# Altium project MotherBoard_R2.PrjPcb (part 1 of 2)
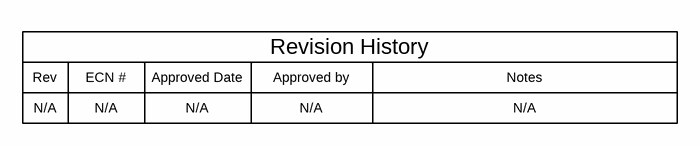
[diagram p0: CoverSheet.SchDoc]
CopyrightYear: 2020; PCB_Layout: Ramesh Ramamoorthy; PCB_Rev: E2; PRJ_Customer: EV Traction; PRJ_Engineer: Ramesh Ramamoorthy; PRJ_Number: EVT_001; PRJ_Title: EV Traction Control Mother Board; SCH_Rev: E2; TechSupport: http://www.ti.com/support; TID: TIDM-02009
7 sheets, 208 parts. Net scope: global (net labels, ports and power ports of the same name join across sheets).
Board file: MotherBoard_R2.PcbDoc
Sheets:
  CoverSheet.SchDoc
  Hardware.SchDoc
  ChildBoardMotor_r2.SchDoc
  MotherBoard_r2.SchDoc
  ChildBoardDC-DC_r2.SchDoc
  powerSupplyAndMontior_r1.SchDoc
  ChildBoardComms_r3.SchDoc

## Sheet CoverSheet.SchDoc
size 431 x 279 mm; Date: Not shown in title block; ApprovedBy: Not shown in title block; CheckedBy: Not shown in title block; Author: Not shown in title block; CompanyName: Not shown in title block; Engineer: Not shown in title block; Organization: Not shown in title block; Address1: Not shown in title block; Address2: Not shown in title block; Address3: Not shown in title block; Address4: Not shown in title block; DocumentNumber: 1; Revision: Use project parameter SCH_Rev; SheetNumber: 1; SheetTotal: 3; PageSetup: Record=PageOptions¦CenterHorizontal=True¦CenterVertical=True¦PrintScale=1.00¦XCorrection=1.00¦YCorrection=1.00¦PrintKind=0¦BorderSize=5000000¦LeftOffset=0¦BottomOffset=0¦Orientation=2¦PaperLength=1000¦PaperWidth=1000¦Scale=100¦PaperSource=15¦PrintQuality=600¦MediaType=1¦DitherType=10¦PaperKind=Letter¦PrintScaleMode=1

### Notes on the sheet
- Rev
- N/A
- ECN #
- Approved Date
- Approved by
- Revision History
- Notes

## Sheet Hardware.SchDoc
size 431 x 279 mm; Date: Not shown in title block; ApprovedBy: Not shown in title block; CheckedBy: Not shown in title block; Author: Not shown in title block; CompanyName: Not shown in title block; Engineer: Not shown in title block; Organization: Not shown in title block; Address1: Not shown in title block; Address2: Not shown in title block; Address3: Not shown in title block; Address4: Not shown in title block; DocumentNumber: 3; Revision: Use project parameter SCH_Rev; SheetNumber: 3; SheetTotal: 3; PageSetup: Record=PageOptions¦CenterHorizontal=True¦CenterVertical=True¦PrintScale=1.00¦XCorrection=1.00¦YCorrection=1.00¦PrintKind=0¦BorderSize=5000000¦LeftOffset=0¦BottomOffset=0¦Orientation=2¦PaperLength=1000¦PaperWidth=1000¦Scale=100¦PaperSource=15¦PrintQuality=600¦MediaType=1¦DitherType=10¦PaperKind=Letter¦PrintScaleMode=1
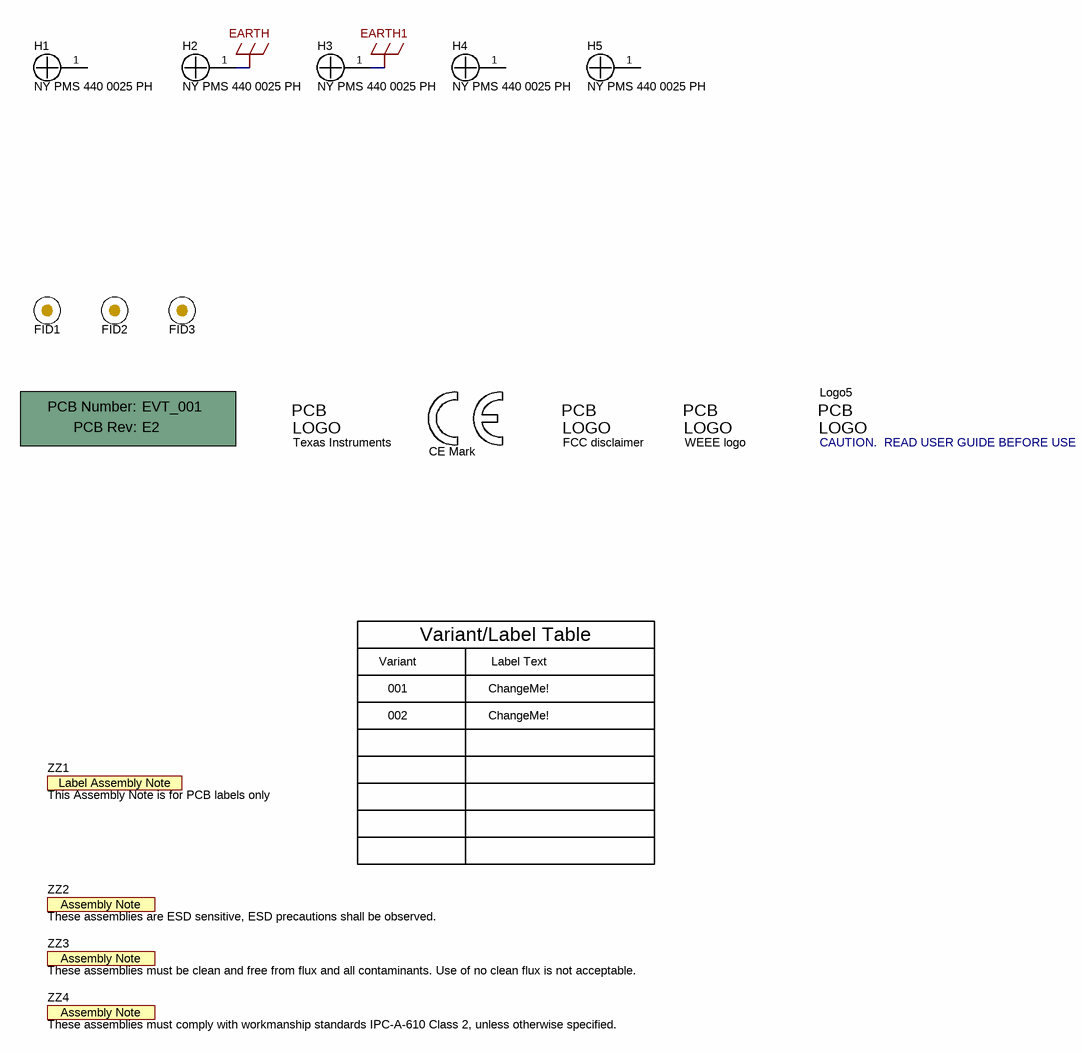
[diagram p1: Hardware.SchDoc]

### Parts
!PCB  Printed Circuit Board  (value not drawn)  (mechanical)
FID1  Fiducial  [Fiducial10-20]  (value not drawn)
FID2  Fiducial  [Fiducial10-20]  (value not drawn)
FID3  Fiducial  [Fiducial10-20]  (value not drawn)
H1  NY PMS 440 0025 PH  [NY PMS 440 0025 PH]
H2  NY PMS 440 0025 PH  [NY PMS 440 0025 PH]
H3  NY PMS 440 0025 PH  [NY PMS 440 0025 PH]
H4  NY PMS 440 0025 PH  [NY PMS 440 0025 PH]
H5  NY PMS 440 0025 PH  [NY PMS 440 0025 PH]
Logo1  Texas Instruments  [TI_Stacked_Overlay_Medium]  (no BOM)
Logo2  CE Mark  [CE_Mark_5mm]  (no BOM)
Logo3  FCC disclaimer  [FCC_disclaimer]  (no BOM)
Logo4  WEEE logo  [WEEE_Minimum]  (no BOM)
Logo5  CAUTION.  READ USER GUIDE BEFORE USE  [IEC_Caution_Small]  (no BOM)
ZZ1  This Assembly Note is for PCB labels only  [AssemblyNoteLabel]  (no BOM)
ZZ2  These assemblies are ESD sensitive, ESD precautions shall be observed.  [AssemblyNote]  (no BOM)
ZZ3  These assemblies must be clean and free from flux and all contaminants. Use of no clean flux is not acceptable.  [AssemblyNote]  (no BOM)
ZZ4  These assemblies must comply with workmanship standards IPC-A-610 Class 2, unless otherwise specified.  [AssemblyNote]  (no BOM)

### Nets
EARTH: H2.1
EARTH1: H3.1

Not connected (* = marked no-connect by the designer): H1 1; H4 1; H5 1

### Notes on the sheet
- Variant
- Variant/Label Table
- Label Text
- 001
- 002
- ChangeMe!

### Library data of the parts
!PCB = CMP-0003618-2: Manufacturer: Any; PartNumber: EVT_001
FID1-FID3 = CMP-0077181-1: Fiducial mark.  There is nothing to buy or mount.
H1-H5 = CMP-0003617-1: Machine Screw, Round, #4-40 x 1/4, Nylon, Philips panhead; Manufacturer: B&F Fastener Supply; CompType: Hardware
Logo1 = CMP-0074838-1: Texas Instrument Corporate Signature; SymbolCreator: a0412235; Lib Reference: TI_Logo; Library Reference: Logo
Logo2 = CMP-0074844-1: SymbolCreator: a0412235
Logo3 = CMP-0074847-1: FCC_disclaimer; Library Reference: Logo
Logo4 = CMP-0074769-1
Logo5 = CMP-0074836-1: IEC 61010-1 Caution Warning; SymbolCreator: a0412235; Lib Reference: IEC_Caution
ZZ1 = CMP-0003616-3
ZZ2 = CMP-0077236-1
ZZ3 = CMP-0077237-1
ZZ4 = CMP-0077238-1

## Sheet ChildBoardMotor_r2.SchDoc
size 431 x 279 mm; Date: Not shown in title block; ApprovedBy: Not shown in title block; CheckedBy: Not shown in title block; Author: Not shown in title block; CompanyName: Not shown in title block; Engineer: Not shown in title block; Organization: Not shown in title block; Address1: Not shown in title block; Address2: Not shown in title block; Address3: Not shown in title block; Address4: Not shown in title block; DocumentNumber: 2; Revision: Use project parameter SCH_Rev; SheetNumber: 2; SheetTotal: 3; PageSetup: Record=PageOptions¦CenterHorizontal=True¦CenterVertical=True¦PrintScale=1.00¦XCorrection=1.00¦YCorrection=1.00¦PrintKind=0¦BorderSize=5000000¦LeftOffset=0¦BottomOffset=0¦Orientation=2¦PaperLength=1000¦PaperWidth=1000¦Scale=100¦PaperSource=15¦PrintQuality=600¦MediaType=1¦DitherType=10¦PaperKind=Letter¦PrintScaleMode=1
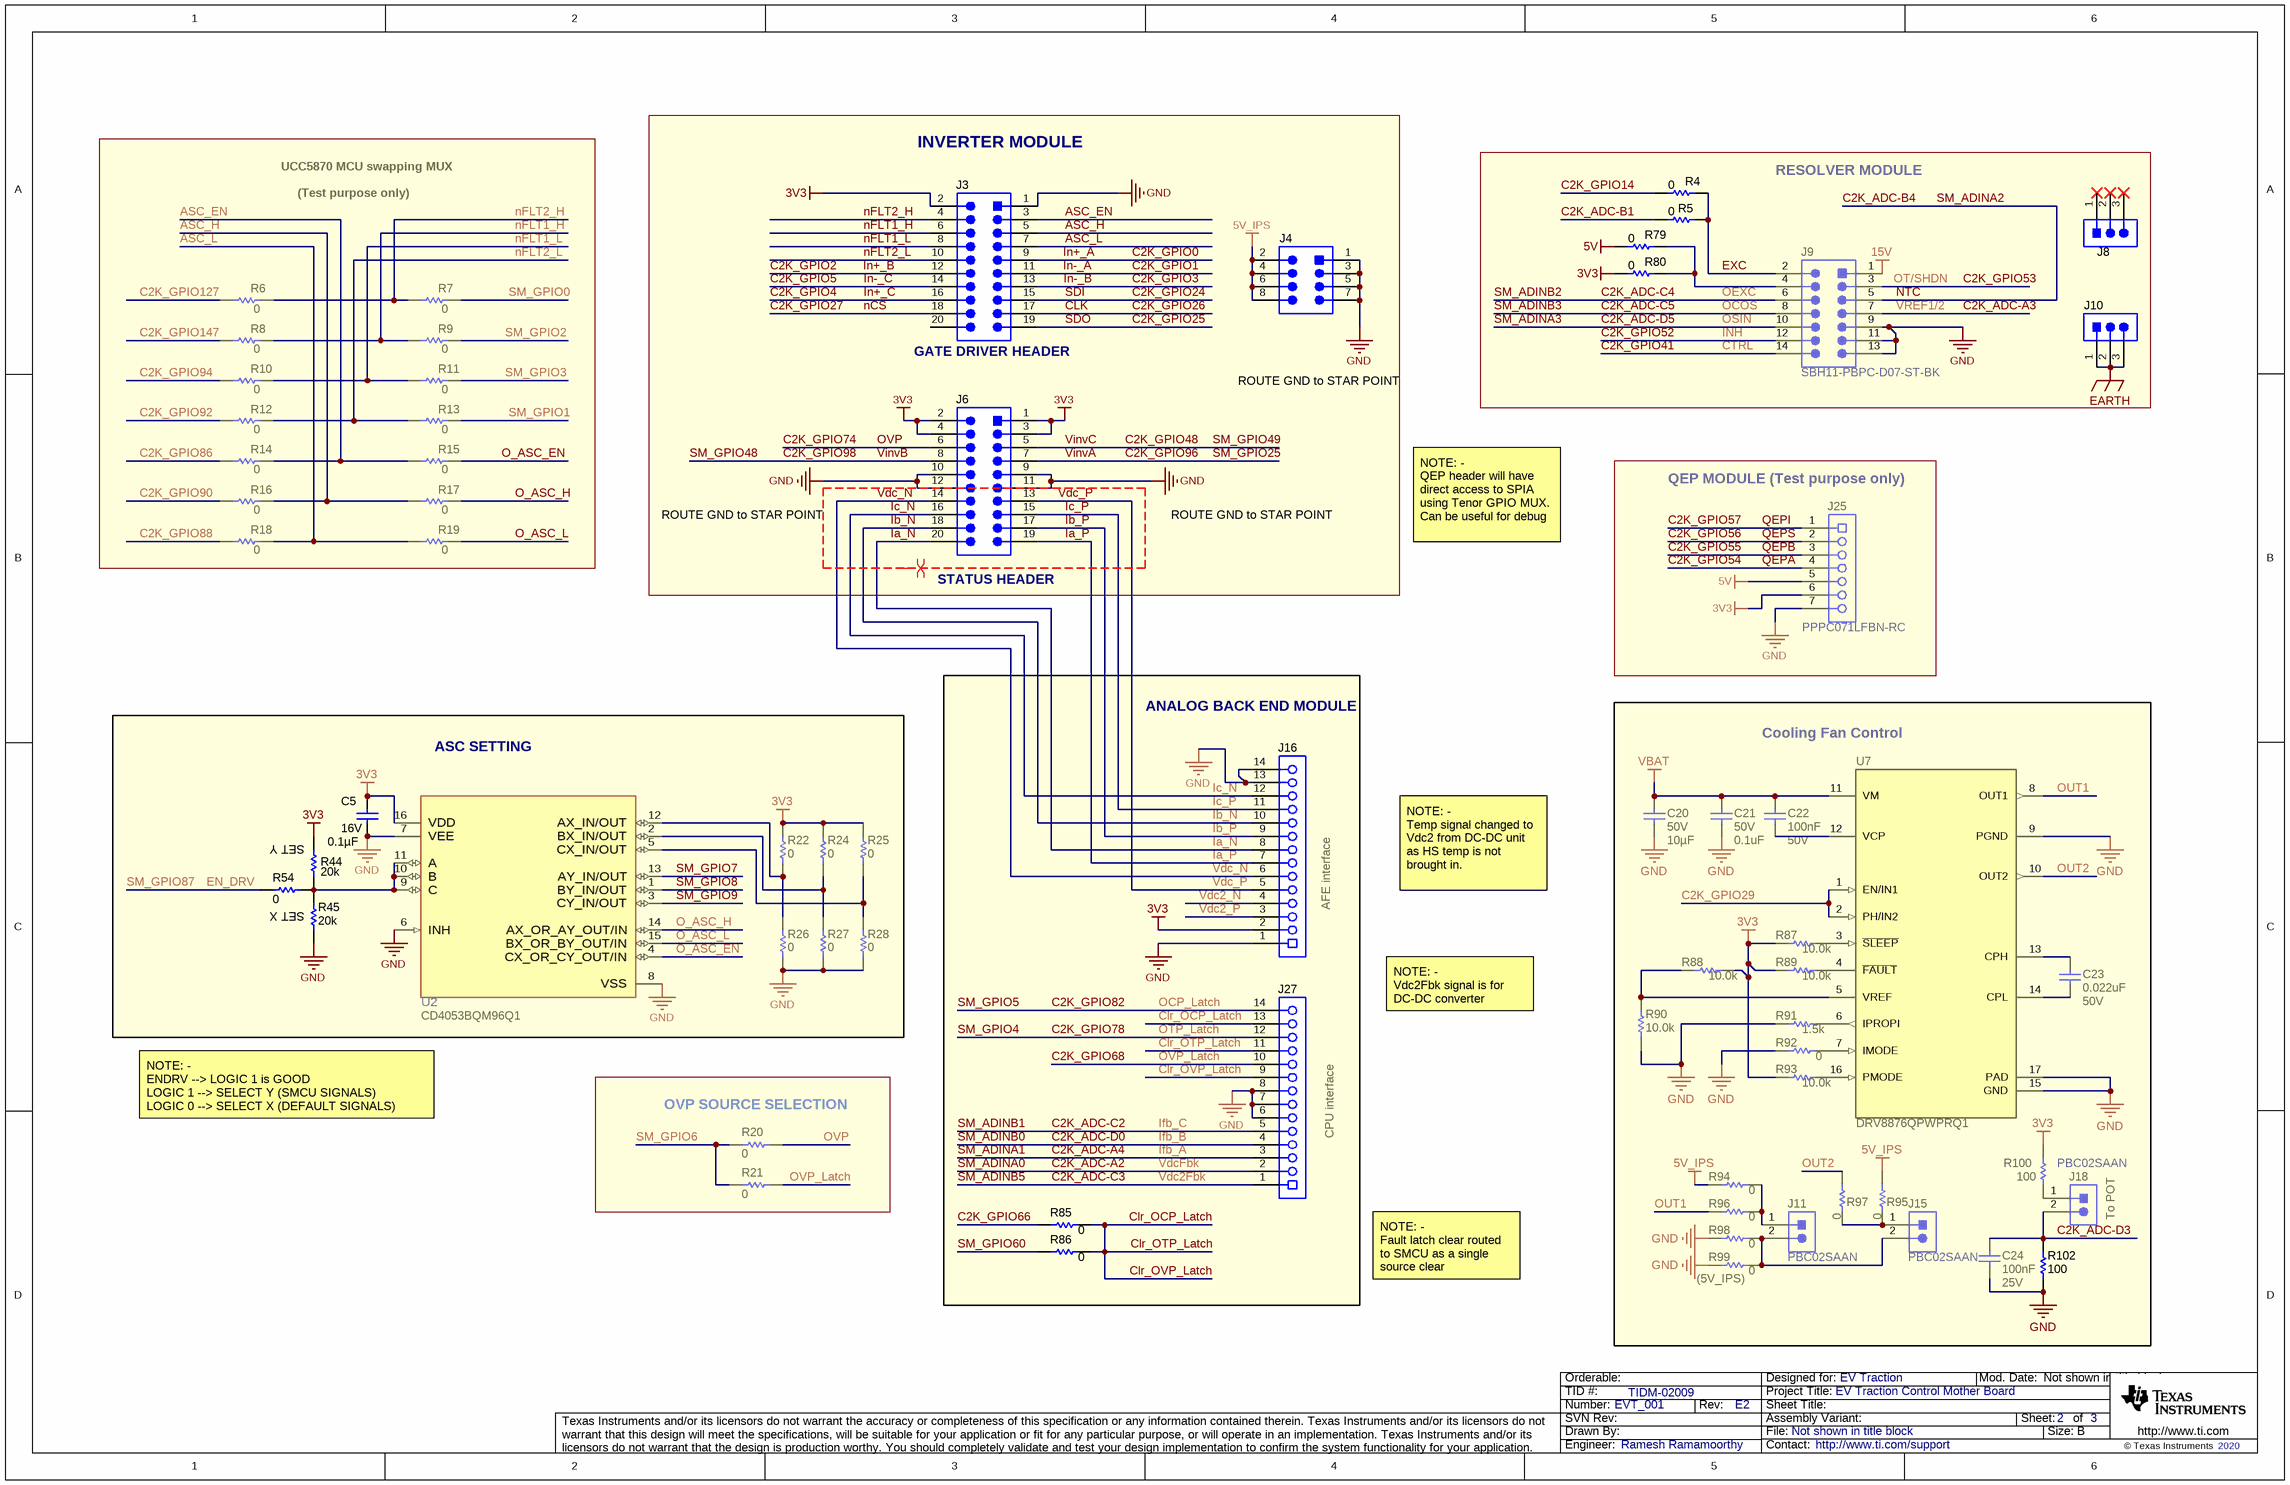
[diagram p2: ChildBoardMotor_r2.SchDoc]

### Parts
C5  VDC_V: 16V  ValueDisplayed: 0.1µF  [1206]  (hidden comment: 1206YC104KAT2A)
C20  VDC_V: 50V  ValueDisplayed: 10µF  [1210_280]  (hidden comment: UMJ325KB7106MMHP)
C21  VDC_V: 50V  ValueDisplayed: 0.1uF  [1206]  (hidden comment: GRM319R71H104KA01D)
C22  Cap_F: 100nF  VDC_V: 50V  [0603L]  (hidden comment: 885012206095)
C23  ValueDisplayed: 0.022uF  VDC_V: 50V  [0603L]  (hidden comment: 885012206091)
C24  Cap_F: 100nF  VDC_V: 25V  [0805_HV]  (hidden comment: SR0805X7R104K1NT95(F)#M123A)
J3  SBH11-PBPC-D10-RA-BK  [Sullins_SBH11-xxxC-D10-RA]  (value not drawn)
J4  61300821021  [Wurth_61300821021]  (value not drawn)
J6  SBH11-PBPC-D10-RA-BK  [Sullins_SBH11-xxxC-D10-RA]  (value not drawn)
J8  61300311121  [WURTH_61300311121]  (value not drawn)
J9  SBH11-PBPC-D07-ST-BK  [CONN_SBH11-PBPC-D07-ST-BK]
J10  61300311121  [WURTH_61300311121]  (value not drawn)
J11  PBC02SAAN  [Sullins_PBC02SAAN]
J15  PBC02SAAN  [Sullins_PBC02SAAN]
J16  SSW-114-01-G-S  [Samtec_SSW-114-01-x-S]  (value not drawn)
J18  PBC02SAAN  [Sullins_PBC02SAAN]
J25  PPPC071LFBN-RC  [Sullins_xPxC071LFBN]
J27  SSW-114-01-G-S  [Samtec_SSW-114-01-x-S]  (value not drawn)
R4  ValueDisplayed: 0  [0805_HV]  (hidden comment: ERJ-6GEY0R00V)
R5  ValueDisplayed: 0  [0805_HV]  (hidden comment: ERJ-6GEY0R00V)
R6  ValueDisplayed: 0  [0805_HV]  (hidden comment: ERJ-6GEY0R00V)
R7  ValueDisplayed: 0  [0805_HV]  (hidden comment: ERJ-6GEY0R00V)
R8  ValueDisplayed: 0  [0805_HV]  (hidden comment: ERJ-6GEY0R00V)
R9  ValueDisplayed: 0  [0805_HV]  (hidden comment: ERJ-6GEY0R00V)
R10  ValueDisplayed: 0  [0805_HV]  (hidden comment: ERJ-6GEY0R00V)
R11  ValueDisplayed: 0  [0805_HV]  (hidden comment: ERJ-6GEY0R00V)
R12  ValueDisplayed: 0  [0805_HV]  (hidden comment: ERJ-6GEY0R00V)
R13  ValueDisplayed: 0  [0805_HV]  (hidden comment: ERJ-6GEY0R00V)
R14  ValueDisplayed: 0  [0805_HV]  (hidden comment: ERJ-6GEY0R00V)
R15  ValueDisplayed: 0  [0805_HV]  (hidden comment: ERJ-6GEY0R00V)
R16  ValueDisplayed: 0  [0805_HV]  (hidden comment: ERJ-6GEY0R00V)
R17  ValueDisplayed: 0  [0805_HV]  (hidden comment: ERJ-6GEY0R00V)
R18  ValueDisplayed: 0  [0805_HV]  (hidden comment: ERJ-6GEY0R00V)
R19  ValueDisplayed: 0  [0805_HV]  (hidden comment: ERJ-6GEY0R00V)
R20  ValueDisplayed: 0  [1206]  (hidden comment: RCA12060000ZSEA)
R21  ValueDisplayed: 0  [1206]  (hidden comment: RCA12060000ZSEA)
R22  ValueDisplayed: 0  [0805_HV]  (hidden comment: ERJ-6GEY0R00V)
R24  ValueDisplayed: 0  [0805_HV]  (hidden comment: ERJ-6GEY0R00V)
R25  ValueDisplayed: 0  [0805_HV]  (hidden comment: ERJ-6GEY0R00V)
R26  ValueDisplayed: 0  [0805_HV]  (hidden comment: ERJ-6GEY0R00V)
R27  ValueDisplayed: 0  [0805_HV]  (hidden comment: ERJ-6GEY0R00V)
R28  ValueDisplayed: 0  [0805_HV]  (hidden comment: ERJ-6GEY0R00V)
R44  ValueDisplayed: 20k  [0805_HV]  (hidden comment: ERJ-6GEYJ203V)
R45  ValueDisplayed: 20k  [0805_HV]  (hidden comment: ERJ-6GEYJ203V)
R54  ValueDisplayed: 0  [0805_HV]  (hidden comment: ERJ-6GEY0R00V)
R79  ValueDisplayed: 0  [0805_HV]  (hidden comment: ERJ-6GEY0R00V)
R80  ValueDisplayed: 0  [0805_HV]  (hidden comment: ERJ-6GEY0R00V)
R85  ValueDisplayed: 0  [1206]  (hidden comment: RCA12060000ZSEA)
R86  ValueDisplayed: 0  [1206]  (hidden comment: RCA12060000ZSEA)
R87  ValueDisplayed: 10.0k  [0603L]  (hidden comment: ERA-3ARW103V)
R88  ValueDisplayed: 10.0k  [0603L]  (hidden comment: ERA-3ARW103V)
R89  ValueDisplayed: 10.0k  [0603L]  (hidden comment: ERA-3ARW103V)
R90  ValueDisplayed: 10.0k  [0603L]  (hidden comment: ERA-3ARW103V)
R91  ValueDisplayed: 1.5k  [0603L]  (hidden comment: CRCW06031K50JNEA)
R92  ValueDisplayed: 0  [0603L]  (hidden comment: ERJ-3GEY0R00V)
R93  ValueDisplayed: 10.0k  [0603L]  (hidden comment: ERA-3ARW103V)
R94  ValueDisplayed: 0  [0603L]  (hidden comment: ERJ-3GEY0R00V)
R95  ValueDisplayed: 0  [0603L]  (hidden comment: ERJ-3GEY0R00V)
R96  ValueDisplayed: 0  [0603L]  (hidden comment: ERJ-3GEY0R00V)
R97  ValueDisplayed: 0  [0603L]  (hidden comment: ERJ-3GEY0R00V)
R98  ValueDisplayed: 0  [0603L]  (hidden comment: ERJ-3GEY0R00V)
R99  ValueDisplayed: 0  [0603L]  (hidden comment: ERJ-3GEY0R00V)
R100  ValueDisplayed: 100  [0805_HV]  (hidden comment: CRCW0805100RFKEA)
R102  ValueDisplayed: 100  [0805_HV]  (hidden comment: CRCW0805100RFKEA)
U2  CD4053BQM96Q1  [D0016A-MFG]
U7  DRV8876QPWPRQ1  [PWP0016J_N]

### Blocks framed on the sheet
INVERTER MODULE: J3 J4 J6
RESOLVER MODULE: J8-J10 R4 R5 R79 R80
QEP MODULE (Test purpose only): J25
ANALOG BACK END MODULE: J16 J27 R85 R86
ASC SETTING: C5 R22 R24-R28 R44 R45 R54 U2
Cooling Fan Control: C20-C24 J11 J15 J18 R87-R100 R102 U7
OVP SOURCE SELECTION: R20 R21

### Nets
3V3: C5.1 J3.2 J6.1 J6.2 J6.3 J6.4 J16.2 J25.6 R22.2 R24.2 R25.2 R44.2 R80.1 R87.1 R88.2 R89.1 R93.1 R100.2 U2.16(VDD)
5V: J25.5 R79.1
5V_IPS: J4.2 J4.4 J4.6 J4.8 R94.1 R95.1
15V: J9.1
EARTH: J10.1 J10.2 J10.3
GND: C5.2 C20.2 C21.2 C24.1 J3.1 J4.1 J4.3 J4.5 J4.7 J6.9 J6.10 J6.11 J6.12 J9.9 J9.11 J9.13 J16.1 J16.13 J16.14 J25.7 J27.6 J27.7 J27.8 R26.1 R27.1 R28.1 R45.1 R90.1 R91.1 R92.1 R98.1 R99.1 R102.1 U2.6(INH) U2.7(VEE) U2.8(VSS) U7.9(PGND) U7.15(GND) U7.17(PAD)
VBAT: C20.1 C21.1 C22.1 U7.11(VM)
ASC_EN: J3.3 R14.2 R15.1
ASC_H: J3.5 R16.2 R17.1
ASC_L: J3.7 R18.2 R19.1
C2K_ADC-A2: J27.2  [also labelled SM_ADINA0, VdcFbk]
C2K_ADC-A3: J9.7  [also labelled VREF1/2]
C2K_ADC-A4: J27.3  [also labelled Ifb_A, SM_ADINA1]
C2K_ADC-B1: R5.1
C2K_ADC-B4: J9.5  [also labelled NTC, SM_ADINA2]
C2K_ADC-C2: J27.5  [also labelled Ifb_C, SM_ADINB1]
C2K_ADC-C3: J27.1  [also labelled SM_ADINB5, Vdc2Fbk]
C2K_ADC-C4: J9.6  [also labelled OEXC, SM_ADINB2]
C2K_ADC-C5: J9.8  [also labelled OCOS, SM_ADINB3]
C2K_ADC-D0: J27.4  [also labelled Ifb_B, SM_ADINB0]
C2K_ADC-D3: C24.2 J18.2 R102.2
C2K_ADC-D5: J9.10  [also labelled OSIN, SM_ADINA3]
C2K_GPIO0: J3.9  [also labelled In+_A]
C2K_GPIO1: J3.11  [also labelled In-_A]
C2K_GPIO2: J3.12  [also labelled In+_B]
C2K_GPIO3: J3.13  [also labelled In-_B]
C2K_GPIO4: J3.16  [also labelled In+_C]
C2K_GPIO5: J3.14  [also labelled In-_C]
C2K_GPIO14: R4.1
C2K_GPIO24: J3.15  [also labelled SDI]
C2K_GPIO25: J3.19  [also labelled SDO]
C2K_GPIO26: J3.17  [also labelled CLK]
C2K_GPIO27: J3.18  [also labelled nCS]
C2K_GPIO29: U7.1(EN/IN1) U7.2(PH/IN2)
C2K_GPIO41: J9.14  [also labelled CTRL]
C2K_GPIO48: J6.5  [also labelled SM_GPIO49, VinvC]
C2K_GPIO52: J9.12  [also labelled INH]
C2K_GPIO53: J9.3  [also labelled OT/SHDN]
C2K_GPIO54: J25.4  [also labelled QEPA]
C2K_GPIO55: J25.3  [also labelled QEPB]
C2K_GPIO56: J25.2  [also labelled QEPS]
C2K_GPIO57: J25.1  [also labelled QEPI]
C2K_GPIO66: R85.1
C2K_GPIO68: J27.10 R21.2  [also labelled OVP_Latch]
C2K_GPIO74: J6.6 R20.2  [also labelled OVP]
C2K_GPIO78: J27.12  [also labelled OTP_Latch, SM_GPIO4]
C2K_GPIO82: J27.14  [also labelled OCP_Latch, SM_GPIO5]
C2K_GPIO86: R14.1
C2K_GPIO88: R18.1
C2K_GPIO90: R16.1
C2K_GPIO92: R12.1
C2K_GPIO94: R10.1
C2K_GPIO96: J6.7  [also labelled SM_GPIO25, VinvA]
C2K_GPIO98: J6.8  [also labelled SM_GPIO48, VinvB]
C2K_GPIO127: R6.1
C2K_GPIO147: R8.1
Clr_OCP_Latch: J27.9 J27.11 J27.13 R85.2 R86.2  [also labelled Clr_OTP_Latch, Clr_OVP_Latch]
EN_DRV: R54.2  [also labelled SM_GPIO87]
EXC: J9.2 R4.2 R5.2
Ia_N: J6.20 J16.8
Ia_P: J6.19 J16.7
Ib_N: J6.18 J16.10
Ib_P: J6.17 J16.9
Ic_N: J6.16 J16.12
Ic_P: J6.15 J16.11
nFLT1_H: J3.6 R8.2 R9.1
nFLT1_L: J3.8 R10.2 R11.1
nFLT2_H: J3.4 R6.2 R7.1
nFLT2_L: J3.10 R12.2 R13.1
O_ASC_EN: R15.2 U2.4(CX_OR_CY_OUT/IN)
O_ASC_H: R17.2 U2.14(AX_OR_AY_OUT/IN)
O_ASC_L: R19.2 U2.15(BX_OR_BY_OUT/IN)
OUT1: R96.1 U7.8(OUT1)
OUT2: R97.1 U7.10(OUT2)
SM_GPIO0: R7.2
SM_GPIO1: R13.2
SM_GPIO2: R9.2
SM_GPIO3: R11.2
SM_GPIO6: R20.1 R21.1
SM_GPIO7: U2.13(AY_IN/OUT)
SM_GPIO8: U2.1(BY_IN/OUT)
SM_GPIO9: U2.3(CY_IN/OUT)
SM_GPIO60: R86.1
Vdc2_N: J16.4
Vdc2_P: J16.3
Vdc_N: J6.14 J16.6
Vdc_P: J6.13 J16.5
NetC22_2: C22.2 U7.12(VCP)
NetC23_1: C23.1 U7.13(CPH)
NetC23_2: C23.2 U7.14(CPL)
NetJ9_4: J9.4 R79.2 R80.2
NetJ11_1: J11.1 R94.2 R96.2
NetJ11_2: J11.2 J15.2 R98.2 R99.2
NetJ15_1: J15.1 R95.2 R97.2
NetJ18_1: J18.1 R100.1
NetR22_1: R22.1 R26.2 U2.12(AX_IN/OUT)
NetR24_1: R24.1 R27.2 U2.2(BX_IN/OUT)
NetR25_1: R25.1 R28.2 U2.5(CX_IN/OUT)
NetR44_1: R44.1 R45.2 R54.1 U2.9(C) U2.10(B) U2.11(A)
NetR87_2: R87.2 U7.3(~{SLEEP})
NetR88_1: R88.1 R90.2 U7.5(VREF)
NetR89_2: R89.2 U7.4(~{FAULT})
NetR91_2: R91.2 U7.6(IPROPI)
NetR92_2: R92.2 U7.7(IMODE)
NetR93_2: R93.2 U7.16(PMODE)

Not connected (* = marked no-connect by the designer): J3 20; J8 1* 2* 3*

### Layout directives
differential pair: Ia_N, Ia_P, Ib_N, Ib_P, Ic_N, Ic_P, Vdc_N, Vdc_P

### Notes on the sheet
- UCC5870 MCU swapping MUX
- (Test purpose only)
- (near J3) GATE DRIVER HEADER
- ROUTE GND to STAR POINT
- NOTE: -
  QEP header will have direct access to SPIA using Tenor GPIO MUX. Can be useful for debug
- (near J6) STATUS HEADER
- (near R44) SET Y
- (near J16) AFE interface
- NOTE: -
  Temp signal changed to Vdc2 from DC-DC unit as HS temp is not brought in.
- SET X
- NOTE: -
  Vdc2Fbk signal is for DC-DC converter
- (near J27) CPU interface
- NOTE: -
  ENDRV --> LOGIC 1 is GOOD
  LOGIC 1 --> SELECT Y (SMCU SIGNALS)
  LOGIC 0 --> SELECT X (DEFAULT SIGNALS)
- (near J18) To POT
- NOTE: -
  Fault latch clear routed to SMCU as a single source clear
- (near R99) (5V_IPS)

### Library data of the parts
C5 = CMP-0860522-1: CAP, CERM, 0.1 µF, 16 V,+/- 10%, X7R, 1206; Manufacturer: AVX; SizeArea_mm2: 5.12; SizeX_mm: 3.2; Value: 0.1uF; SizeAreaWB_mm2: 10.92; Cap_F: 100nF; SizeZ_mm: 1.35; AEC Category: Q200; Polarized: N; U/M: EA; SizeY_mm: 1.6; TaMin_C: -55°C; TaMax_C: 125°C
C20 = CMP-0082302-1: CAP, CERM, 10 µF, 50 V,+/- 20%, X7R, AEC-Q200 Grade 1, 1210; Manufacturer: Taiyo Yuden; SizeAreaWB_mm2: 14.7; SizeArea_mm2: 8; AEC Qualified: Y; AEC Category: Q200; Value: 10uF; TaMax_C: 125°C; SizeZ_mm: 2.8; AEC Grade: 1; Polarized: N; TaMin_C: -55°C; SizeY_mm: 2.5; U/M: EA; SizeX_mm: 3.2; Cap_Case: 1210
C21 = CMP-0008876-1: CAP, CERM, 0.1 uF, 50 V, +/- 10%, X7R, 1206; Manufacturer: MuRata; TaMin_C: -55°C; ESR_ohm: 0.01; Polarized: N; SizeAreaWB_mm2: 10.92; Value1: 0.01 ohm; U/M: EA; Value: 0.1uF; TaMax_C: 125°C; SizeZ_mm: 1.35; SizeX_mm: 3.2; SizeY_mm: 1.6; SizeArea_mm2: 5.12; Cap_F: 100nF; IRMS_A: 900mA; AEC Category: Q200
C22 = CMP-0006837-4: CAP, CERM, 0.1 uF, 50 V, +/- 10%, X7R, 0603; Manufacturer: Wurth Elektronik; Polarized: N; Value: 0.1uF; U/M: EA; Value1: Unknown; TaMin_C: -55°C; TaMax_C: 125°C; Cap_Case: 0603; SizeArea_mm2: 1.28; SizeAreaWB_mm2: 4.68; SizeX_mm: 1.6; SizeY_mm: 0.8; SizeZ_mm: 1; AEC Category: Q200
C23 = CMP-0006836-4: CAP, CERM, 0.022 uF, 50 V, +/- 10%, X7R, 0603; Manufacturer: Wurth Elektronik; Polarized: N; U/M: EA; Cap_F: 22nF; Value1: Unknown; TaMin_C: -55°C; TaMax_C: 125°C; Cap_Case: 0603; SizeArea_mm2: 1.28; SizeAreaWB_mm2: 4.68; SizeX_mm: 1.6; SizeY_mm: 0.8; SizeZ_mm: 1; AEC Category: Q200
C24 = CMP-0079722-1: CAP, CERM, 0.1 µF, 25 V,+/- 10%, X7R, 0805; Manufacturer: Presidio Components; TaMin_C: -55°C; Polarized: N; SizeAreaWB_mm2: 6.75; U/M: EA; Value: 0.1uF; TaMax_C: 125°C; SizeZ_mm: 1.45; SizeX_mm: 2; SizeY_mm: 1.25; Cap_Case: 0805; SizeArea_mm2: 2.5; AEC Category: Q200; ValueDisplayed: 0.1µF
J3 J6 = CMP-0054719-2: Header (Shrouded), 2.54mm, 10x2, Gold, TH; Manufacturer: Sullins Connector Solutions; Current_A: 3A; Shrouded: Y; Gender: Male; Voltage_V: 1kV; Row_Count: 2; RowSpacing_mm: 2.54
J4 = CMP-0054803-2: Header, 2.54mm, 4x2, Gold, R/A, TH; Manufacturer: Wurth Elektronik; Current_A: 3A; Shrouded: N; Gender: Male; Voltage_V: 250V; Row_Count: 2; RowSpacing_mm: 2.54; Cert_UL: Y
J8 J10 = CMP-0054796-2: Header, 2.54 mm, 3x1, Gold, TH; Manufacturer: Wurth Elektronik; Pitch_mm: 2.54; Green_Lifecycle: Active; Cert_UL: Y; Shrouded: N; Green_REACh: Passed; Gender: Male; Row_Count: 1
J9 = CMP-0054695-2: Header (shrouded), 100 mil, 7x2, Gold, TH; Manufacturer: Sullins Connector Solutions; Green_REACh: Incomplete; Green_Lifecycle: Not Set
J11 J15 J18 = CMP-0054566-1: Header, 100mil, 2x1, Gold, TH; Manufacturer: Sullins Connector Solutions; CNHeader: TRUE; Current_A: 3A; Green_Lifecycle: Active; Shrouded: N; Gender: Male; Green_REACh: Passed; Voltage_V: 1.8kV; Row_Count: 1; Pitch_mm: 2.54; CT: FALSE; Cert_UL: Y
J16 J27 = CMP-0055711-1: Receptacle, 2.54mm, 14x1, Gold, TH; Manufacturer: Samtec; CNHeader: FALSE; Current_A: 4.7A; Gender: Female; Cert_CSA: Y; Voltage_V: 465V; CompType: Socket Strip; Row_Count: 1; Pitch_mm: 2.54; CT: TRUE
J25 = CMP-0054674-1: Receptacle, 2.54mm, 7x1, Gold, TH; Manufacturer: Sullins Connector Solutions; CNHeader: FALSE; Current_A: 3A; Gender: Female; Voltage_V: 250V; CompType: Socket Strip; Row_Count: 1; Pitch_mm: 2.54; ContactFinish: Tin; CT: TRUE; Cert_UL: Y
R4-R19 R22 R24-R28 R54 R79 R80 = CMP-0020616-3: RES, 0, 5%, 0.125 W, AEC-Q200 Grade 0, 0805; Manufacturer: Panasonic; Power_W: 125mW; TempCo: 600 ppm/C; Value_Code: 0000; Value: 0; EIA_Code: E24; SizeX_mm: 2; SizeY_mm: 1.25; SizeZ_mm: 1.45; Value2: 0.125W; SizeArea_mm2: 2.5; AEC Qualified: Y; VDC_V: 150V; AEC Category: Q200; SizeAreaWB_mm2: 6.75
R20 R21 R85 R86 = CMP-0018760-1: RES, 0, 5%, 0.25 W, AEC-Q200 Grade 0, 1206; Manufacturer: Vishay-Dale; Power_W: 250mW; TempCo: ppm/C; Value_Code: 0000; U/M: EA; Value: 0; EIA_Code: E24; SizeX_mm: 3.2; SizeY_mm: 1.6; SizeZ_mm: 1.35; Value2: 0.25W; SizeArea_mm2: 5.12; AEC Qualified: Y; AEC Category: Q200
R44 R45 = CMP-0020671-1: RES, 20 k, 5%, 0.125 W, 0805; Manufacturer: Panasonic; Power_W: 125mW; TempCo: 200 ppm/C; Value_Code: 20k0; U/M: EA; Value: 20k; EIA_Code: E24; SizeX_mm: 2; SizeY_mm: 1.25; SizeZ_mm: 1.45; Value2: 0.125W; SizeArea_mm2: 2.5; VDC_V: 150V; AEC Category: Q200
R87-R90 R93 = CMP-0086251-1: RES, 10.0 k, 0.05%, 0.1 W, AEC-Q200 Grade 0, 0603; Manufacturer: Panasonic; Res_ohm: 10k; Value: 10.0k; SizeY_mm: 0.8; SizeArea_mm2: 1.28; SizeAreaWB_mm2: 4.68; AEC Grade: 0; Power_W: 100mW; SizeX_mm: 1.6; Value2: 0.1W; Value_Code: 10k0; SizeZ_mm: 1; AEC Qualified: Y; AEC Category: Q200; TempCo: 10 ppm/C
R91 = CMP-0025733-4: RES, 1.5 k, 5%, 0.1 W, AEC-Q200 Grade 0, 0603; Manufacturer: Vishay-Dale; Value: 1.5k; Value_Code: 1k50; Power_W: 100mW; Value2: 0.1W; VDC_V: 75V; TempCo: 200 ppm/C; SizeArea_mm2: 1.28; SizeX_mm: 1.6; SizeY_mm: 0.8; SizeZ_mm: 1; EIA_Code: E24; AEC Category: Q200; AEC Qualified: Y; AEC Grade: 0
R92 R94-R99 = CMP-0025874-3: RES, 0, 5%, 0.1 W, 0603; Manufacturer: Panasonic; Value: 0; Value_Code: 0000; Power_W: 100mW; Value2: 0.1W; VDC_V: 50V; TempCo: 600 ppm/C; EIA_Code: E24; U/M: EA; SizeArea_mm2: 1.28; SizeX_mm: 1.6; SizeY_mm: 0.8; SizeZ_mm: 1; AEC Category: Q200
R100 R102 = CMP-0020835-2: RES, 100, 1%, 0.125 W, 0805; Manufacturer: Vishay-Dale; Power_W: 125mW; TempCo: 100 ppm/C; Value_Code: 100R; U/M: EA; Value: 100; EIA_Code: E96; SizeX_mm: 2; SizeY_mm: 1.25; SizeZ_mm: 1.45; Value2: 0.125W; SizeArea_mm2: 2.5; VDC_V: 150V; AEC Category: Q200
U2 = CMP-0088292-1: 3 Circuit IC Switch 2:1 240Ohm 16-SOIC; Manufacturer: Texas Instruments; On State Resistance: 125Ω; -3Db Bandwith: 30MHz; AEC Qualified: Yes; TJmax_C: +150°C; Nominal Supply Current: 0.04-0.08uA; Standoff Height: 0.1mm; PositionCount: 3; AEC Grade: Grade 1; Max Supply Voltage: 20V; Min Supply Voltage: 3V; SizeZ_mm: 1.75mm
U7 = CMP-0080455-1: Automotive Grade H-Bridge Motor Driver With Integrated Current Sense and Regulation, PWP0016J (TSSOP-16); Alternate Manufacturer: Texas Instruments; SizeAreaWB_mm2: 58.8; SizeZ_mm: 1.2; SizeX_mm: 6.4; SizeY_mm: 5; SizeArea_mm2: 32; CompType: IC; AEC Qualified: Y; AEC Category: Q200

## Sheet MotherBoard_r2.SchDoc
size A3; Date: Not shown in title block; ApprovedBy: Not shown in title block; CheckedBy: Not shown in title block; Author: Not shown in title block; CompanyName: Not shown in title block; Engineer: Not shown in title block; Organization: Not shown in title block; Address1: Not shown in title block; Address2: Not shown in title block; Address3: Not shown in title block; Address4: Not shown in title block; DocumentNumber: 2; Revision: Use project parameter SCH_Rev; SheetNumber: 2; SheetTotal: 3; PageSetup: Record=PageOptions¦CenterHorizontal=True¦CenterVertical=True¦PrintScale=1.00¦XCorrection=1.00¦YCorrection=1.00¦PrintKind=0¦BorderSize=5000000¦LeftOffset=0¦BottomOffset=0¦Orientation=2¦PaperLength=1000¦PaperWidth=1000¦Scale=100¦PaperSource=15¦PrintQuality=600¦MediaType=1¦DitherType=10¦PaperKind=Letter¦PrintScaleMode=1
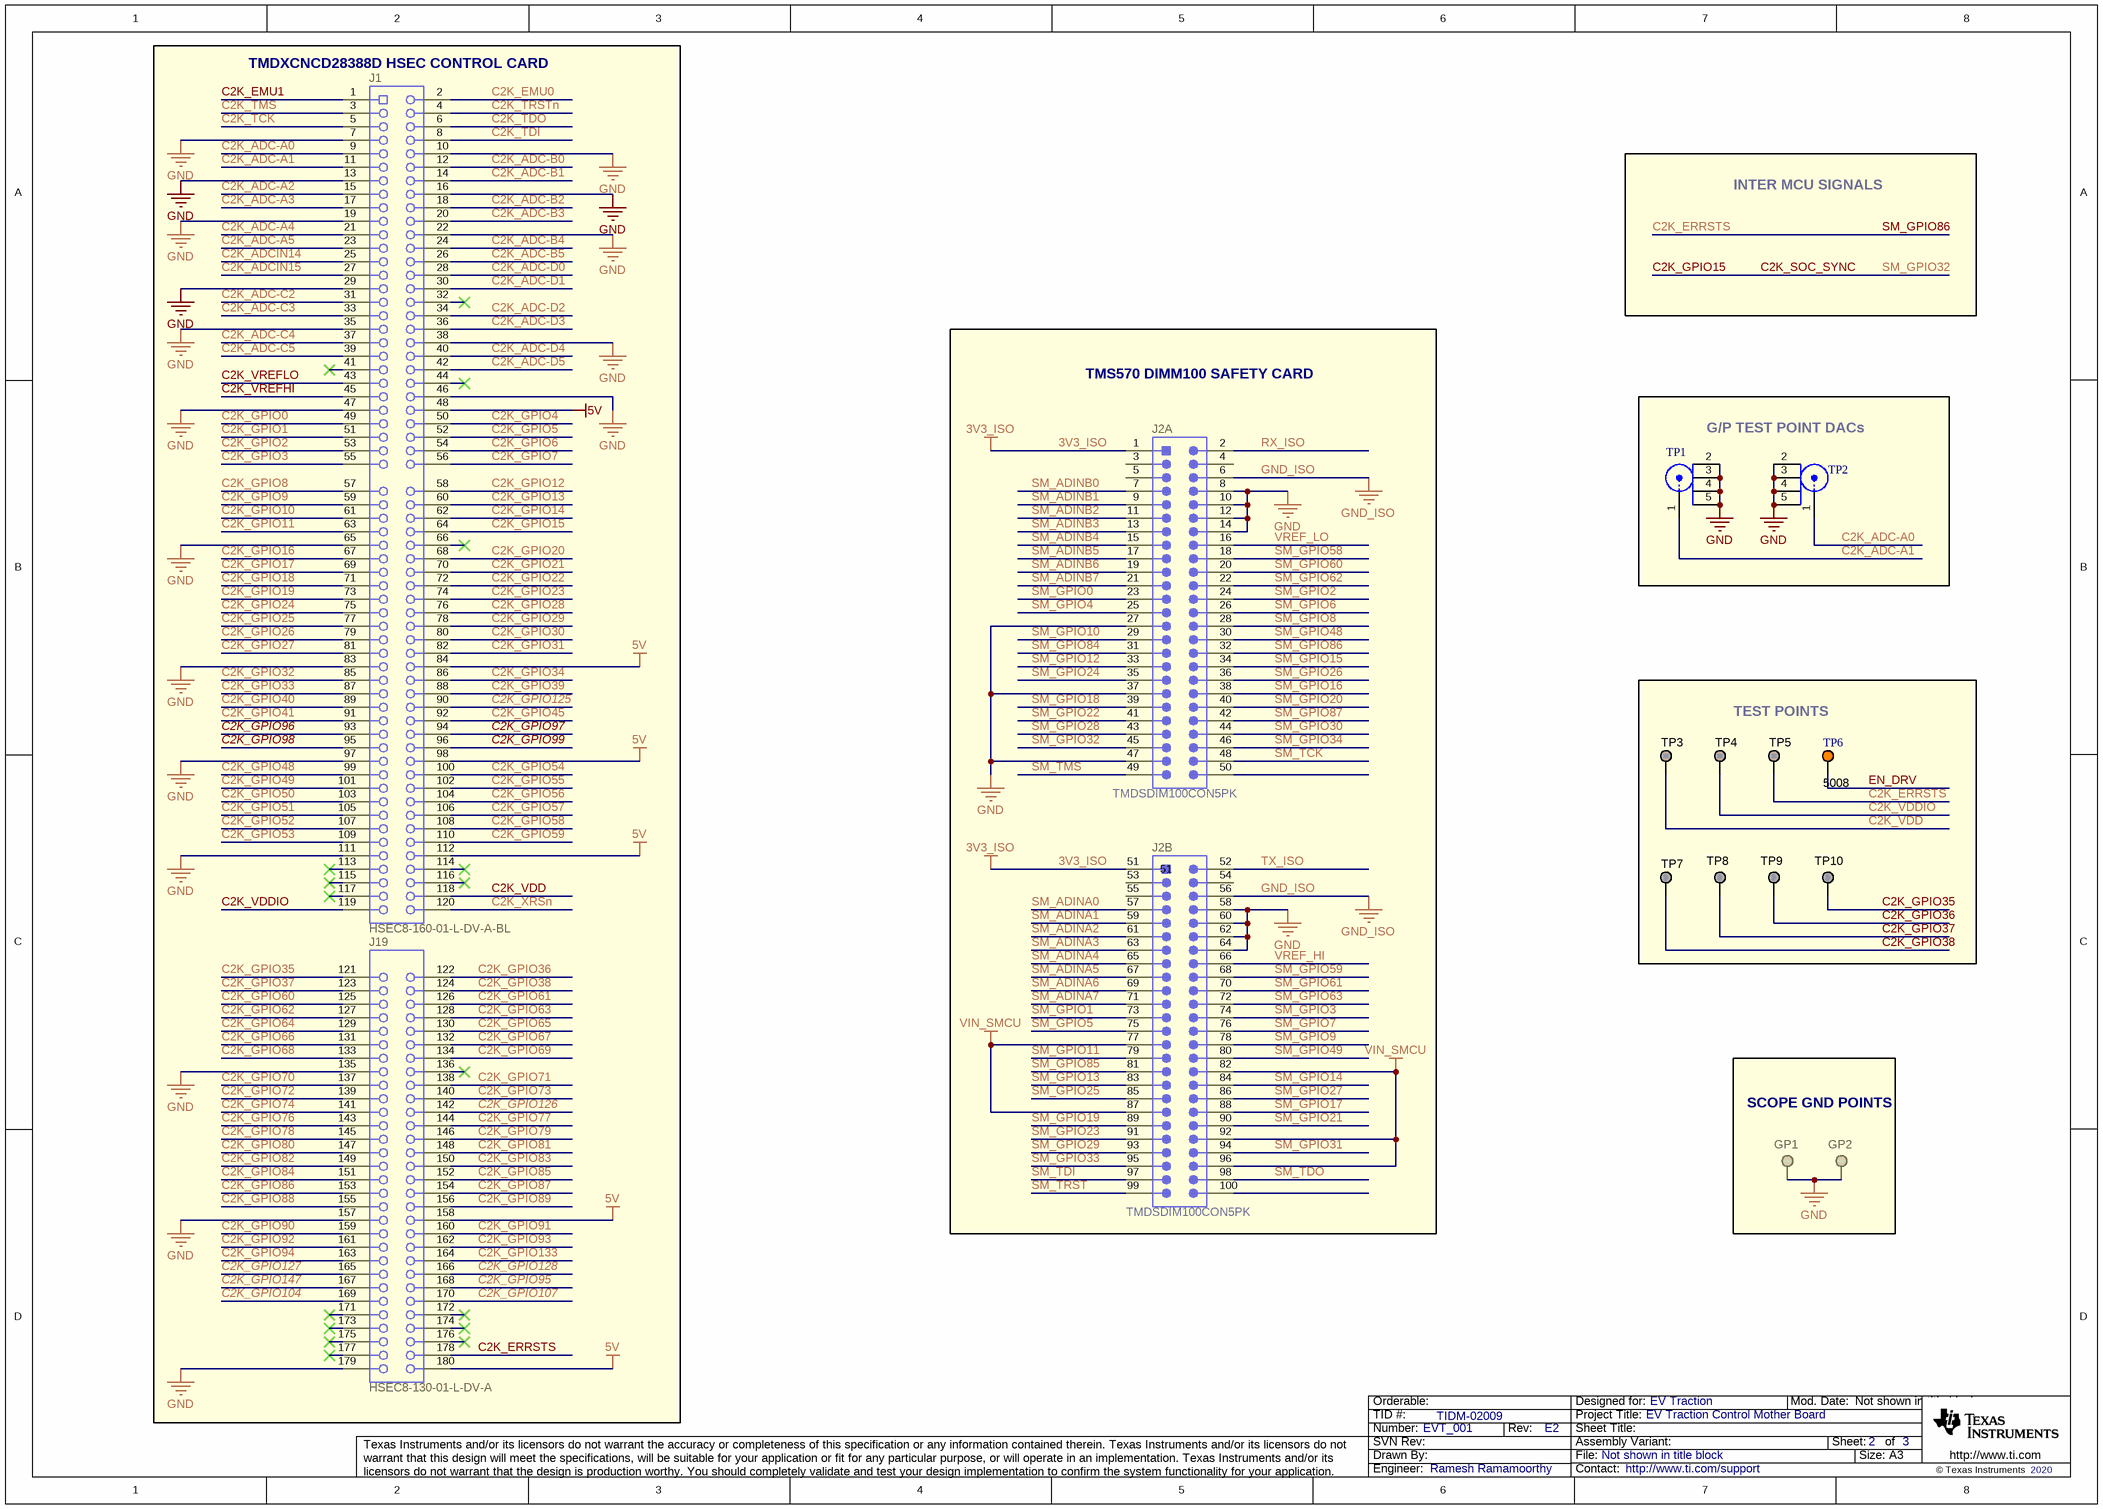
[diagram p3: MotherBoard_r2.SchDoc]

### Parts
GP1  TESTPOINT  [TESTPOINT]  (value not drawn)  (no BOM)
GP2  TESTPOINT  [TESTPOINT]  (value not drawn)  (no BOM)
J1  HSEC8-160-01-L-DV-A-BL  [controlCARD-120HSEC]
J2  TMDSDIM100CON5PK  [TI_TMDSDIM100CON5PK]  (parts A,B of 2)
J19  HSEC8-130-01-L-DV-A  [controlCARD-180HSEC-60pinAddon]
TP1  734151471  [Molex_0734151471]  (value not drawn)
TP2  734151471  [Molex_0734151471]  (value not drawn)
TP3  TP_H0.45P0.75  [TP_H045P075]  (value not drawn)  (no BOM)
TP4  TP_H0.45P0.75  [TP_H045P075]  (value not drawn)  (no BOM)
TP5  TP_H0.45P0.75  [TP_H045P075]  (value not drawn)  (no BOM)
TP6  5008  [Keystone5008]
TP7  TESTPOINT  [TESTPOINT]  (value not drawn)  (no BOM)
TP8  TESTPOINT  [TESTPOINT]  (value not drawn)  (no BOM)
TP9  TESTPOINT  [TESTPOINT]  (value not drawn)  (no BOM)
TP10  TESTPOINT  [TESTPOINT]  (value not drawn)  (no BOM)

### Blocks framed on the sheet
TMDXCNCD28388D HSEC CONTROL CARD: J1 J19
TMS570 DIMM100 SAFETY CARD: J2
G/P TEST POINT DACs: TP1 TP2
TEST POINTS: TP3-TP10
SCOPE GND POINTS: GP1 GP2

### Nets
3V3_ISO: J2.1 J2.51
5V: J1.48 J1.84 J1.98 J1.112 J19.158 J19.180
C2K_VDD: J1.118 TP3.1
C2K_VDDIO: J1.119 TP4.1
C2K_VREFHI: J1.45
GND: GP1.1 GP2.1 J1.7 J1.10 J1.13 J1.16 J1.19 J1.22 J1.29 J1.35 J1.38 J1.46 J1.47 J1.65 J1.83 J1.97 J1.111 J2.8 J2.10 J2.12 J2.14 J2.27 J2.37 J2.47 J2.58 J2.60 J2.62 J2.64 J19.135 J19.157 J19.179 TP1.2 TP1.3 TP1.4 TP1.5 TP2.2 TP2.3 TP2.4 TP2.5
GND_ISO: J2.6 J2.56
VIN_SMCU: J2.77 J2.82 J2.87 J2.92 J2.96
C2K_ADC-A0: J1.9 TP2.1
C2K_ADC-A1: J1.11 TP1.1
C2K_ADC-A2: J1.15 J2.57  [also labelled SM_ADINA0]
C2K_ADC-A3: J1.17
C2K_ADC-A4: J1.21 J2.59  [also labelled SM_ADINA1]
C2K_ADC-A5: J1.23
C2K_ADC-B0: J1.12 J2.19  [also labelled SM_ADINB6]
C2K_ADC-B1: J1.14
C2K_ADC-B2: J1.18
C2K_ADC-B3: J1.20
C2K_ADC-B4: J1.24 J2.61  [also labelled SM_ADINA2]
C2K_ADC-B5: J1.26
C2K_ADC-C2: J1.31 J2.9  [also labelled SM_ADINB1]
C2K_ADC-C3: J1.33 J2.17  [also labelled SM_ADINB5]
C2K_ADC-C4: J1.37 J2.11  [also labelled SM_ADINB2]
C2K_ADC-C5: J1.39 J2.13  [also labelled SM_ADINB3]
C2K_ADC-D0: J1.28 J2.7  [also labelled SM_ADINB0]
C2K_ADC-D1: J1.30
C2K_ADC-D2: J1.34 J2.21  [also labelled SM_ADINB7]
C2K_ADC-D3: J1.36
C2K_ADC-D4: J1.40
C2K_ADC-D5: J1.42 J2.63  [also labelled SM_ADINA3]
C2K_ADCIN14: J1.25
C2K_ADCIN15: J1.27
C2K_EMU0: J1.2
C2K_EMU1: J1.1
C2K_ERRSTS: J2.32 J19.178 TP5.1  [also labelled SM_GPIO86]
C2K_GPIO0: J1.49
C2K_GPIO1: J1.51
C2K_GPIO2: J1.53
C2K_GPIO3: J1.55
C2K_GPIO4: J1.50
C2K_GPIO5: J1.52
C2K_GPIO6: J1.54
C2K_GPIO7: J1.56
C2K_GPIO8: J1.57
C2K_GPIO9: J1.59
C2K_GPIO10: J1.61
C2K_GPIO11: J1.63
C2K_GPIO12: J1.58
C2K_GPIO13: J1.60
C2K_GPIO14: J1.62
C2K_GPIO15: J1.64 J2.45  [also labelled C2K_SOC_SYNC, SM_GPIO32]
C2K_GPIO16: J1.67
C2K_GPIO17: J1.69
C2K_GPIO18: J1.71
C2K_GPIO19: J1.73
C2K_GPIO20: J1.68
C2K_GPIO21: J1.70
C2K_GPIO22: J1.72
C2K_GPIO23: J1.74
C2K_GPIO24: J1.75
C2K_GPIO25: J1.77
C2K_GPIO26: J1.79
C2K_GPIO27: J1.81
C2K_GPIO28: J1.76
C2K_GPIO29: J1.78
C2K_GPIO30: J1.80
C2K_GPIO31: J1.82
C2K_GPIO32: J1.85
C2K_GPIO33: J1.87
C2K_GPIO34: J1.86
C2K_GPIO35: J19.121 TP10.1
C2K_GPIO36: J19.122 TP9.1
C2K_GPIO37: J19.123 TP8.1
C2K_GPIO38: J19.124 TP7.1
C2K_GPIO39: J1.88
C2K_GPIO40: J1.89
C2K_GPIO41: J1.91
C2K_GPIO45: J1.92
C2K_GPIO48: J1.99 J2.80  [also labelled SM_GPIO49]
C2K_GPIO49: J1.101
C2K_GPIO50: J1.103
C2K_GPIO51: J1.105
C2K_GPIO52: J1.107
C2K_GPIO53: J1.109
C2K_GPIO54: J1.100
C2K_GPIO55: J1.102
C2K_GPIO56: J1.104
C2K_GPIO57: J1.106
C2K_GPIO58: J1.108
C2K_GPIO59: J1.110
C2K_GPIO60: J19.125
C2K_GPIO61: J19.126
C2K_GPIO62: J19.127
C2K_GPIO63: J19.128
C2K_GPIO64: J19.129  [project net C2K PS EN]
C2K_GPIO65: J19.130
C2K_GPIO66: J19.131
C2K_GPIO67: J19.132
C2K_GPIO68: J19.133
C2K_GPIO69: J19.134
C2K_GPIO70: J2.43 J19.137  [also labelled SM_GPIO28]
C2K_GPIO71: J2.93 J19.138  [also labelled SM_GPIO29]
C2K_GPIO72: J19.139
C2K_GPIO73: J19.140
C2K_GPIO74: J19.141
C2K_GPIO76: J19.143
C2K_GPIO77: J19.144
C2K_GPIO78: J2.25 J19.145  [also labelled SM_GPIO4]
C2K_GPIO79: J19.146
C2K_GPIO80: J19.147
C2K_GPIO81: J19.148
C2K_GPIO82: J2.75 J19.149  [also labelled SM_GPIO5]
C2K_GPIO83: J19.150
C2K_GPIO84: J19.151
C2K_GPIO85: J19.152
C2K_GPIO86: J19.153
C2K_GPIO87: J19.154
C2K_GPIO88: J19.155
C2K_GPIO89: J19.156
C2K_GPIO90: J19.159
C2K_GPIO91: J19.160
C2K_GPIO92: J19.161
C2K_GPIO93: J19.162
C2K_GPIO94: J19.163
C2K_GPIO95: J19.168
C2K_GPIO96: J1.93 J2.85  [also labelled SM_GPIO25]
C2K_GPIO97: J1.94
C2K_GPIO98: J1.95 J2.30  [also labelled SM_GPIO48]
C2K_GPIO99: J1.96
C2K_GPIO104: J19.169
C2K_GPIO107: J19.170
C2K_GPIO125: J1.90
C2K_GPIO126: J19.142
C2K_GPIO127: J19.165
C2K_GPIO128: J19.166
C2K_GPIO133: J19.164
C2K_GPIO147: J19.167
C2K_TCK: J1.5
C2K_TDI: J1.8
C2K_TDO: J1.6
C2K_TMS: J1.3
C2K_TRSTn: J1.4
C2K_VREFLO: J1.43
C2K_XRSn: J1.120
EN_DRV: J2.42 TP6.1  [also labelled SM_GPIO87]
RX_ISO: J2.2
SM_ADINA4: J2.65
SM_ADINA5: J2.67
SM_ADINA6: J2.69
SM_ADINA7: J2.71
SM_ADINB4: J2.15
SM_GPIO0: J2.23
SM_GPIO1: J2.73
SM_GPIO2: J2.24
SM_GPIO3: J2.74
SM_GPIO6: J2.26
SM_GPIO7: J2.76
SM_GPIO8: J2.28
SM_GPIO9: J2.78
SM_GPIO10: J2.29
SM_GPIO11: J2.79
SM_GPIO12: J2.33  [project net CAN_GPO2]
SM_GPIO13: J2.83
SM_GPIO14: J2.84  [project net CAN_GPIO1]
SM_GPIO15: J2.34  [project net CAN_nINT]
SM_GPIO16: J2.38
SM_GPIO17: J2.88
SM_GPIO18: J2.39
SM_GPIO19: J2.89
SM_GPIO20: J2.40
SM_GPIO21: J2.90
SM_GPIO22: J2.41
SM_GPIO23: J2.91  [project net SM PS EN]
SM_GPIO24: J2.35  [project net SM C2K RST]
SM_GPIO26: J2.36
SM_GPIO27: J2.86
SM_GPIO30: J2.44  [project net RxD2]
SM_GPIO31: J2.94
SM_GPIO33: J2.95  [project net GPIO_RST]
SM_GPIO34: J2.46  [project net nSTB2]
SM_GPIO58: J2.18
SM_GPIO59: J2.68
SM_GPIO60: J2.20
SM_GPIO61: J2.70
SM_GPIO62: J2.22
SM_GPIO63: J2.72
SM_GPIO84: J2.31
SM_GPIO85: J2.81
SM_TCK: J2.48
SM_TDI: J2.97
SM_TDO: J2.98
SM_TMS: J2.49
SM_TRST: J2.99
TX_ISO: J2.52
VREF_HI: J2.66
VREF_LO: J2.16

Not connected (* = marked no-connect by the designer): J1 32* 41* 44* 66* 113* 114* 115* 116* 117*; J2 3 4 5 50 53 54 55 100; J19 136* 171* 172* 173* 174* 175* 176* 177*

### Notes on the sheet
- INTER MCU SIGNALS

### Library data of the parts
GP1 GP2 TP7-TP10 = CMP-0078143-3: TEST POINT.  No entry in BOM.
J1 = CMP-0003814-2: C2000 controlCARD-120HSEC connector, SMT; Manufacturer: Samtec; Note: The pin numbering does not match Samtec datasheet
J2 = CMP-0075002-1: Connector, DIM 1.27 mm 100 CKTS, An Identical Molex SD-87630-001  obsolete; Manufacturer: Texas Instruments; CT: False
J19 = CMP-0003859-2: C2000 controlCARD-180HSEC (60-pin addon) connector, SMT; Manufacturer: Samtec; Note: The pin numbering does not match Samtec datasheet
TP1 TP2 = CMP-0055255-1: MMCX JACK, 50 Ohm, Gold, TH; Manufacturer: Molex; CNHeader: FALSE; Gender: Female
TP3-TP5 = CMP-0003719-1: Testpoint; Manufacturer: Texas Instruments; CompType: Pad
TP6 = CMP-0055145-1: Test Point, Compact, Orange, TH; Manufacturer: Keystone; CNHeader: FALSE; Green_Lifecycle: Active; Green_REACh: Passed; ContactFinish: Silver; CT: TRUE

## Sheet ChildBoardDC-DC_r2.SchDoc
size 431 x 279 mm; Date: Not shown in title block; ApprovedBy: Not shown in title block; CheckedBy: Not shown in title block; Author: Not shown in title block; CompanyName: Not shown in title block; Engineer: Not shown in title block; Organization: Not shown in title block; Address1: Not shown in title block; Address2: Not shown in title block; Address3: Not shown in title block; Address4: Not shown in title block; DocumentNumber: 2; Revision: Use project parameter SCH_Rev; SheetNumber: 2; SheetTotal: 3; PageSetup: Record=PageOptions¦CenterHorizontal=True¦CenterVertical=True¦PrintScale=1.00¦XCorrection=1.00¦YCorrection=1.00¦PrintKind=0¦BorderSize=5000000¦LeftOffset=0¦BottomOffset=0¦Orientation=2¦PaperLength=1000¦PaperWidth=1000¦Scale=100¦PaperSource=15¦PrintQuality=600¦MediaType=1¦DitherType=10¦PaperKind=Letter¦PrintScaleMode=1
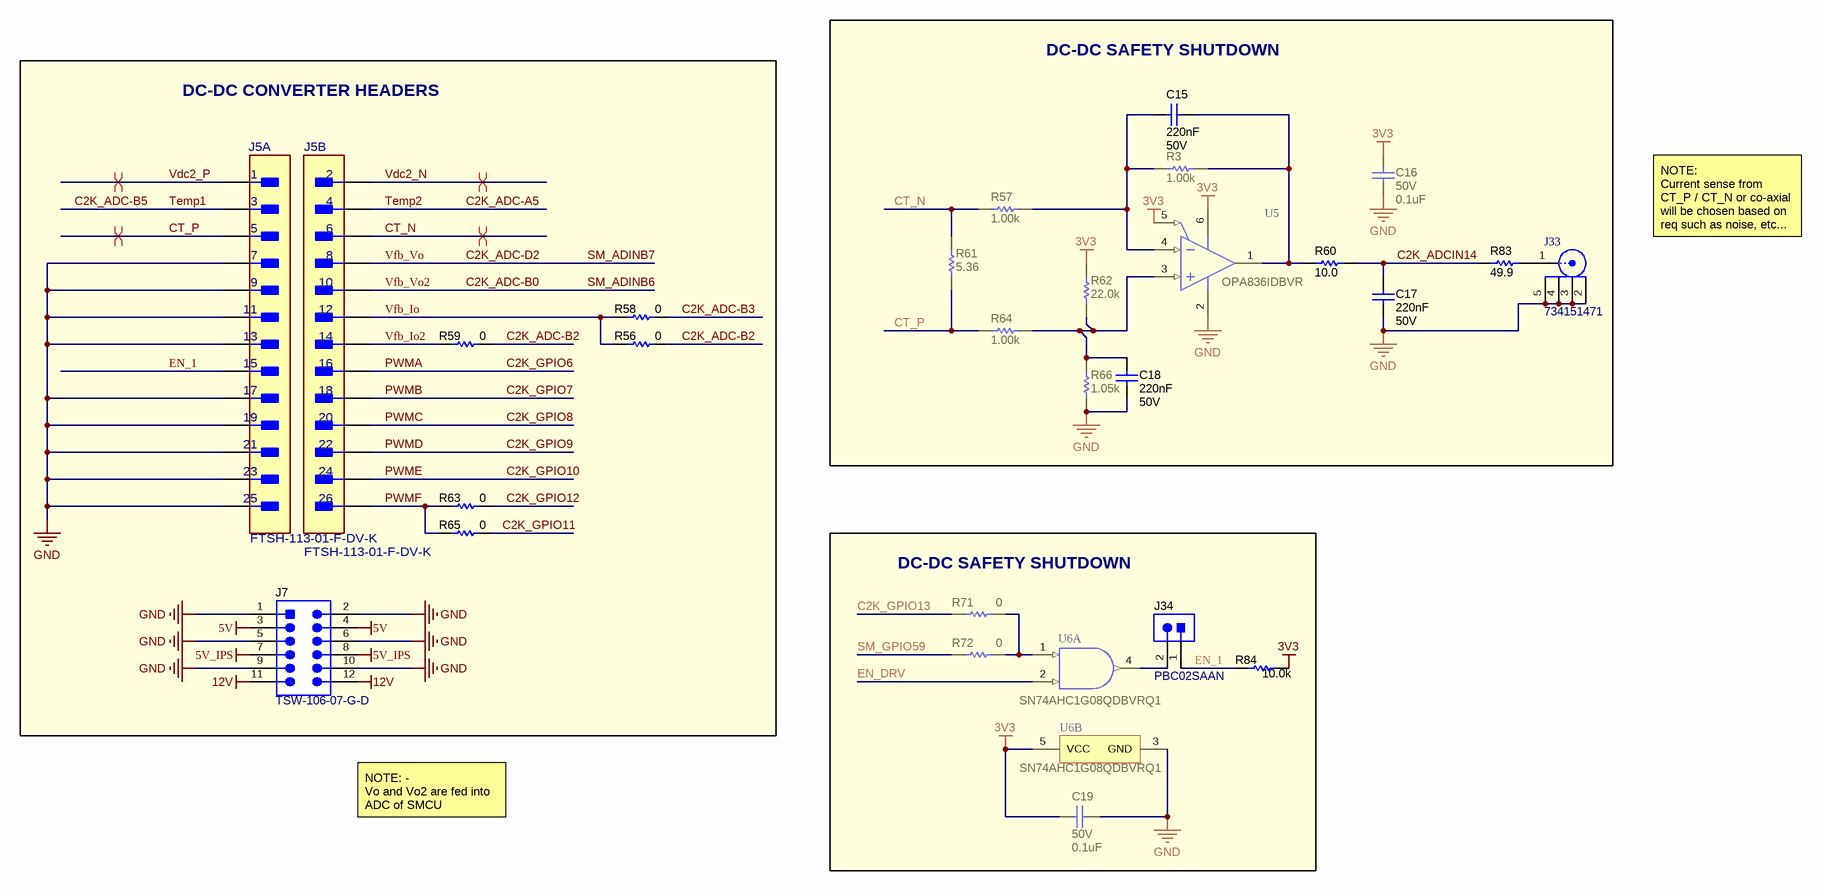
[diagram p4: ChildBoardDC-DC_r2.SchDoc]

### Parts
C15  Cap_F: 220nF  VDC_V: 50V  [0603]  (hidden comment: GCM188R71H224KA64D)
C16  VDC_V: 50V  ValueDisplayed: 0.1uF  [0805_150]  (hidden comment: CEU4J2X7R1H104K125AE)
C17  Cap_F: 220nF  VDC_V: 50V  [0603]  (hidden comment: GCM188R71H224KA64D)
C18  Cap_F: 220nF  VDC_V: 50V  [0603]  (hidden comment: GCM188R71H224KA64D)
C19  VDC_V: 50V  ValueDisplayed: 0.1uF  [0805_150]  (hidden comment: CEU4J2X7R1H104K125AE)
J5  FTSH-113-01-F-DV-K  [FP-FTSH-113-01-F-DV-K_HDR26-MFG]  (parts A,B of 2)
J7  TSW-106-07-G-D  [TSW-106-07-G-D]
J33  734151471  [Molex_0734151471]
J34  PBC02SAAN  [Sullins_PBC02SAAN]
R3  ValueDisplayed: 1.00k  [0603]  (hidden comment: RC0603FR-071KL)
R56  ValueDisplayed: 0  [0603]  (hidden comment: RCS06030000Z0EA)
R57  ValueDisplayed: 1.00k  [0603]  (hidden comment: RC0603FR-071KL)
R58  ValueDisplayed: 0  [0603]  (hidden comment: RCS06030000Z0EA)
R59  ValueDisplayed: 0  [0603]  (hidden comment: RCS06030000Z0EA)
R60  ValueDisplayed: 10.0  [0603]  (hidden comment: CRCW060310R0FKEAHP)
R61  ValueDisplayed: 5.36  [1206]  (hidden comment: CRCW12065R36FKEA)
R62  ValueDisplayed: 22.0k  [0603]  (hidden comment: ERJ-3EKF2202V)
R63  ValueDisplayed: 0  [0603]  (hidden comment: RCS06030000Z0EA)
R64  ValueDisplayed: 1.00k  [0603]  (hidden comment: RC0603FR-071KL)
R65  ValueDisplayed: 0  [0603]  (hidden comment: RCS06030000Z0EA)
R66  ValueDisplayed: 1.05k  [0603]  (hidden comment: RC0603FR-071K05L)
R71  ValueDisplayed: 0  [0603]  (hidden comment: RCS06030000Z0EA)
R72  ValueDisplayed: 0  [0603]  (hidden comment: RCS06030000Z0EA)
R83  ValueDisplayed: 49.9  [0603]  (hidden comment: RC0603FR-0749R9L)
R84  ValueDisplayed: 10.0k  [0603L]  (hidden comment: ERA-3ARW103V)
U5  OPA836IDBVR  [DBV0006A_L]
U6  SN74AHC1G08QDBVRQ1  [DBV0005A_N]  (parts A,B of 2)

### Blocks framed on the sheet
DC-DC SAFETY SHUTDOWN: C15-C18 J33 R3 R57 R60-R62 R64 R66 R83 U5
DC-DC CONVERTER HEADERS: J5 J7 R56 R58 R59 R63 R65
DC-DC SAFETY SHUTDOWN: C19 J34 R71 R72 R84 U6

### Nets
3V3: C16.1 C19.1 R62.2 R84.2 U5.5(~{PD}) U5.6(VS+) U6.5(VCC)
5V: J7.3 J7.4
5V_IPS: J7.7 J7.8
12V: J7.11 J7.12
GND: C16.2 C17.2 C18.2 C19.2 J5.7 J5.9 J5.11 J5.13 J5.17 J5.19 J5.21 J5.23 J5.25 J7.1 J7.2 J7.5 J7.6 J7.9 J7.10 J33.2 J33.3 J33.4 J33.5 R66.1 U5.2(VS-) U6.3(GND)
C2K_ADC-A5: J5.4  [also labelled Temp2]
C2K_ADC-B0: J5.10  [also labelled SM_ADINB6, Vfb_Vo2]
C2K_ADC-B2: R56.2 R59.2
C2K_ADC-B3: R58.2
C2K_ADC-B5: J5.3  [also labelled Temp1]
C2K_ADC-D2: J5.8  [also labelled SM_ADINB7, Vfb_Vo]
C2K_ADCIN14: C17.1 R60.2 R83.1
C2K_GPIO6: J5.16  [also labelled PWMA]
C2K_GPIO7: J5.18  [also labelled PWMB]
C2K_GPIO8: J5.20  [also labelled PWMC]
C2K_GPIO9: J5.22  [also labelled PWMD]
C2K_GPIO10: J5.24  [also labelled PWME]
C2K_GPIO11: R65.2
C2K_GPIO12: R63.2
C2K_GPIO13: R71.1
CT_N: J5.6 R57.1 R61.2
CT_P: J5.5 R61.1 R64.1
EN_1: J5.15 J34.1 R84.1
EN_DRV: U6.2(B)
PWMF: J5.26 R63.1 R65.1
SM_GPIO59: R72.1
Vdc2_N: J5.2
Vdc2_P: J5.1
Vfb_Io: J5.12 R56.1 R58.1
Vfb_Io2: J5.14 R59.1
NetC15_1: C15.1 R3.2 R60.1 U5.1(VOUT)
NetC15_2: C15.2 R3.1 R57.2 U5.4(VIN-)
NetC18_1: C18.1 R62.1 R64.2 R66.2 U5.3(VIN+)
NetJ33_1: J33.1 R83.2
NetJ34_2: J34.2 U6.4(Y)
NetR71_2: R71.2 R72.2 U6.1(A)

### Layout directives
differential pair: CT_N, CT_P, Vdc2_N, Vdc2_P

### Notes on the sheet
- NOTE:
  Current sense from CT_P / CT_N or co-axial will be chosen based on req such as noise, etc...
- NOTE: -
  Vo and Vo2 are fed into ADC of SMCU

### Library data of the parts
C15 C17 C18 = CMP-0007145-4: CAP, CERM, 0.22 uF, 50 V, +/- 10%, X7R, AEC-Q200 Grade 1, 0603; Manufacturer: MuRata; TaMin_C: -55°C; Polarized: N; SizeAreaWB_mm2: 4.68; Value1: Unknown; U/M: EA; Value: 0.22uF; TaMax_C: 125°C; SizeZ_mm: 1; SizeX_mm: 1.6; SizeY_mm: 0.8; SizeArea_mm2: 1.28; AEC Qualified: Y; AEC Category: Q200
C16 C19 = CMP-0007961-2: CAP, CERM, 0.1 uF, 50 V, +/- 10%, X7R, AEC-Q200 Grade 1, 0805; Manufacturer: TDK; TaMin_C: -55°C; Polarized: N; SizeAreaWB_mm2: 6.75; Value1: Unknown; U/M: EA; Value: 0.1uF; TaMax_C: 125°C; SizeZ_mm: 1.5; SizeX_mm: 2; SizeY_mm: 1.25; Cap_Case: 0805; SizeArea_mm2: 2.5; CompType: Capacitor; AEC Qualified: Y; Cap_F: 100nF; AEC Grade: 1; AEC Category: Q200
J5 = CMP-0089180-1: Manufacturer: Samtec; ContactFinish: Gold,Nickel; AEC Qualified: No; DUT-Pitch_mm: 1.27mm; SizeZ_mm: 6.38mm; Current_A: 3.4A; Row_Count: 2; Conn Orientation: Vertical; Conn Gender: Male
J7 = CMP-0075412-2: Header, 100mil, 6x2, Gold, TH; Manufacturer: Samtec; Pitch_mm: 2.54; Cert_VDE: N; Gender: Male; Cert_CSA: Y; Voltage_V: 550V; Green_REACh: Passed; Current_A: 6.3A; Green_Lifecycle: Active; Row_Count: 2
J33 = CMP-0055255-1: as TP1 on sheet MotherBoard_r2
J34 = CMP-0054566-1: as J11 on sheet ChildBoardMotor_r2
R3 R57 R64 = CMP-0022895-5: RES, 1.00 k, 1%, 0.1 W, 0603; Manufacturer: Yageo; Power_W: 100mW; TempCo: 100 ppm/C; Value_Code: 1k00; Value: 1.00k; EIA_Code: E96; Res_ohm: 1k; SizeX_mm: 1.6; SizeY_mm: 0.8; SizeZ_mm: 1; Value2: 0.1W; SizeArea_mm2: 1.28; AEC Qualified: N; VDC_V: 75V; AEC Category: Q200; SizeAreaWB_mm2: 4.68
R56 R58 R59 R63 R65 R71 R72 = CMP-0081973-1: RES, 0, 0%, 0.25 W, AEC-Q200 Grade 0, 0603; Manufacturer: Vishay-Dale; SizeAreaWB_mm2: 4.68; SizeArea_mm2: 1.28; AEC Qualified: Y; AEC Category: Q200; Value: 0; SizeZ_mm: 1; SizeY_mm: 0.8; Power_W: 250mW; Value2: 0.25W; SizeX_mm: 1.6
R60 = CMP-0022004-4: RES, 10.0, 1%, 0.25 W, AEC-Q200 Grade 0, 0603; Manufacturer: Vishay-Dale; Power_W: 250mW; TempCo: 100 ppm/C; Value_Code: 10R0; Value: 10.0; EIA_Code: E96; Res_ohm: 10; SizeX_mm: 1.6; SizeY_mm: 0.8; SizeZ_mm: 1; Value2: 0.25W; SizeArea_mm2: 1.28; AEC Qualified: Y; VDC_V: 75V; AEC Category: Q200; AEC Grade: 0
R61 = CMP-0017094-3: RES, 5.36, 1%, 0.25 W, AEC-Q200 Grade 0, 1206; Manufacturer: Vishay-Dale; Power_W: 250mW; TempCo: 100 ppm/C; Value_Code: 5R36; Value: 5.36; EIA_Code: E96; SizeX_mm: 3.2; SizeY_mm: 1.6; SizeZ_mm: 1.35; Value2: 0.25W; SizeArea_mm2: 5.12; AEC Qualified: Y; VDC_V: 200V; AEC Category: Q200; AEC Grade: 0
R62 = CMP-0022692-3: RES, 22.0 k, 1%, 0.1 W, AEC-Q200 Grade 0, 0603; Manufacturer: Panasonic; Power_W: 100mW; TempCo: 100 ppm/C; Value_Code: 22k0; U/M: EA; Value: 22.0k; Res_ohm: 22k; SizeX_mm: 1.6; SizeY_mm: 0.8; SizeZ_mm: 1; Value2: 0.1W; SizeArea_mm2: 1.28; AEC Qualified: Y; VDC_V: 50V; AEC Grade: 0; AEC Category: Q200
R66 = CMP-0022865-5: RES, 1.05 k, 1%, 0.1 W, 0603; Manufacturer: Yageo; Power_W: 100mW; TempCo: 100 ppm/C; Value_Code: 1k05; Value: 1.05k; EIA_Code: E96; SizeX_mm: 1.6; SizeY_mm: 0.8; SizeZ_mm: 1; Value2: 0.1W; SizeArea_mm2: 1.28; AEC Qualified: N; VDC_V: 75V; AEC Category: Q200; SizeAreaWB_mm2: 4.68
R83 = CMP-0023143-5: RES, 49.9, 1%, 0.1 W, 0603; Manufacturer: Yageo; Power_W: 100mW; TempCo: 100 ppm/C; Value_Code: 49R9; Value: 49.9; EIA_Code: E96; SizeX_mm: 1.6; SizeY_mm: 0.8; SizeZ_mm: 1; Value2: 0.1W; SizeArea_mm2: 1.28; AEC Qualified: N; VDC_V: 75V; AEC Category: Q200; SizeAreaWB_mm2: 4.68
R84 = CMP-0086251-1: as R87 on sheet ChildBoardMotor_r2
U5 = CMP-0040148-1: Very Low Power, Rail to Rail Out, Negative Rail In, VFB Operational Amplifier, 2.5 to 5.5 V, -40 to 125 degC, 6-pin SOT23 (DBV6), Green (RoHS & no Sb/Br); Manufacturer: Texas Instruments; Iib(Max)(nA): 1000; Io(Typ)(mA): 50; Acl, min stable gain(V/V): 1; Vn at Flatband(Typ)(nV/rtHz): 4.6; Slew Rate(Typ)(V/us): 560; BW @ Acl(MHz): 205; Sub Family: Audio Operational Amplifier, High Output Current Amplifier (>=50mA), High Speed Amplifier (>=50MHz), Low Noise Amp (<=10nV/rtHz), Low Offset Voltage Amplifier (<=500uV), Low Supply Voltage Amplifier (<=2.7V); 3rd Harmonic(dBc): 105; Vio(Max)(mV): 0.4; Settling Time (0.1%)(Typ)(ns): 30; Vs(Min)(V): 2.5; 2nd Harmonic(dBc): 85; Vs(Max)(V): 5.5
U6 = CMP-0051573-2: Automotive Catalog Single 2-Input Positive-AND Gate, DBV0005A (SOT-23-5); Generic Part Number: SN74AHC1G08-Q1; Manufacturer: Texas Instruments; Output Drive (IOL/IOH)(Max)(mA): 50/-50; Output Type: CMOS; Logic: True; Bits(#): 1; Schmitt Trigger: No; VCC(Max)(V): 5.5; Gate Type: AND; VCC(Min)(V): 2; Voltage(Nom)(V): 3.3,5; tpd @ Nom Voltage(Max)(ns): 12.3,7.9; F @ Nom Voltage(Max)(Mhz): 75; ICC @ Nom Voltage(Max)(mA): 0.01; AEC Category: Q200; AEC Qualified: Y; CompType: IC; SizeAreaWB_mm2: 14.82; SizeArea_mm2: 8.12; SizeX_mm: 2.8; SizeY_mm: 2.9; SizeZ_mm: 1.45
